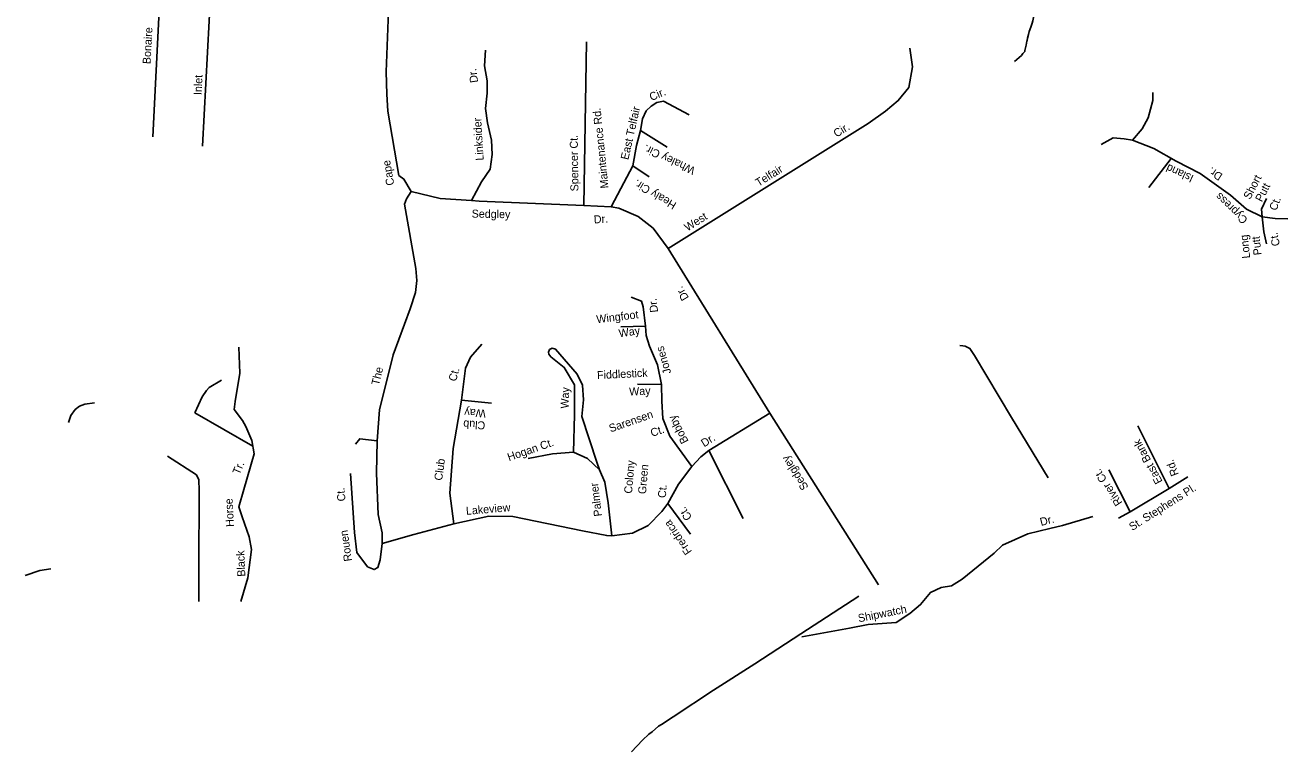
# Model space of a CAD drawing. Extents: x 2308163 to 2335412, y -96774 to 127732.
# Drawn here: x 2321289 to 2322583, y 13023 to 13768 of the extents above; entities that cross this region are included whole.
import ezdxf

# ---------------------------------------------------------------- set-up
doc = ezdxf.new("R2010")
doc.units = 0
doc.layers.add('Old_Level_10', color=7, linetype='Continuous')
doc.layers.add('Old_Level_35', color=7, linetype='Continuous')

msp = doc.modelspace()

# ---------------------------------------------------------------- linework, layer by layer
at = {"layer": 'Old_Level_35'}
for points in [[(2321470.9, 13644.1), (2321479.2, 13805.1), (2321483.9, 13860.9), (2321484.1, 13918.6), (2321488.9, 13978), (2321484.4, 14035), (2321484.8, 14072.5), (2321494.1, 14104.3), (2321497.9, 14132.5), (2321498.4, 14173.8)], [(2321419.9, 13653.8), (2321443.4, 14123.4), (2321438.5, 14164.8)], [(2321684.8, 13597.6), (2321677.3, 13610.4), (2321672.2, 13614.2), (2321660.9, 13680.1), (2321659.9, 13697.4), (2321659.1, 13720.5), (2321661, 13773.8), (2321660.4, 13787.4), (2321658.4, 13821), (2321656.2, 13849.4), (2321657.3, 13864.5), (2321663, 13879.5), (2321675.1, 13895.3), (2321684, 13910.7), (2321692.1, 13931.9), (2321701.8, 13970.3), (2321711.6, 14009.8), (2321724.8, 14060.6), (2321735.9, 14109.5), (2321739.7, 14137)], [(2322316.1, 13752.6), (2322316.7, 13754.8), (2322317.6, 13758.5), (2322318.4, 13761.7), (2322320, 13766.2), (2322321.4, 13770.4), (2322322.2, 13772.7), (2322322.5, 13774.4), (2322322.7, 13775.9), (2322322.5, 13778.1), (2322322.8, 13780.6), (2322321.8, 13790.4), (2322320.2, 13807), (2322318.2, 13825.5), (2322317.3, 13831.8), (2322317.3, 13840), (2322317, 13849.8), (2322317.7, 13866), (2322318.5, 13891.5), (2322320.1, 13927.7), (2322321.1, 13953.3)], [(2321861.7, 13583.4), (2321864.4, 13751.2)], [(2322303.2, 13731.1), (2322310.3, 13737.1), (2322311.8, 13739.1), (2322313.1, 13740.6), (2322313.9, 13741.3), (2322313.9, 13742.3), (2322315.1, 13747.8), (2322315.9, 13751.8), (2322316.1, 13752.6)], [(2321760.9, 13742.6), (2321759.8, 13726.4), (2321762.5, 13711.1), (2321762.5, 13698.6), (2321761, 13682.9), (2321763.1, 13668.2), (2321767.2, 13650.2), (2321767.7, 13635.6), (2321765.6, 13620.4), (2321756.8, 13607.7), (2321746.7, 13588.4)], [(2321948.2, 13539.1), (2322153.3, 13667.4), (2322171, 13679.9), (2322184, 13690.9), (2322194.9, 13704.2), (2322198.8, 13725.5), (2322195.8, 13744.5)], [(2322424.1, 13650.4), (2322434.1, 13661.8), (2322440.3, 13673.2), (2322445.2, 13691.1), (2322444.9, 13699)], [(2321889.9, 13581.9), (2321899.5, 13600.7), (2321911.8, 13623.9), (2321915.7, 13644.7), (2321919.9, 13660.3), (2321921.9, 13672.2), (2321925.8, 13680.5), (2321930.7, 13685), (2321936.6, 13689), (2321943.5, 13690.3), (2321969.7, 13676.3)], [(2321919.9, 13660.3), (2321947.1, 13643.1)], [(2322392.1, 13645.7), (2322404.5, 13652.7), (2322415.7, 13651.8), (2322424.1, 13650.4), (2322446.1, 13641.7), (2322469, 13628.7), (2322493.5, 13616.2), (2322524.6, 13593.9), (2322541.1, 13579.6), (2322557.3, 13571.6), (2322556.5, 13579.6), (2322561.6, 13590.5)], [(2322441, 13601.6), (2322464, 13631.5)], [(2321911.8, 13623.9), (2321928.7, 13612.8)], [(2321684.8, 13597.6), (2321679.8, 13590), (2321678, 13584.8), (2321689.4, 13518.5), (2321690.5, 13506.4), (2321689, 13493.9), (2321683.8, 13477.3), (2321666.4, 13430.2), (2321652.4, 13373.7), (2321649.7, 13341.9), (2321649.1, 13308.9), (2321650.8, 13266.5), (2321654.9, 13247.5), (2321655, 13236.5), (2321652.9, 13219.8), (2321650.5, 13212), (2321646.8, 13210), (2321640.1, 13212.9), (2321629, 13227.4), (2321626.6, 13247.9), (2321622.4, 13308.3)], [(2321972.4, 13315.5), (2321981.7, 13325.6), (2321989.8, 13332.2), (2322052.4, 13370.3), (2321948.2, 13539.1), (2321932.7, 13560), (2321917.4, 13572.1), (2321897.7, 13580.6), (2321889.9, 13581.9), (2321861.7, 13583.4), (2321754.5, 13587.6), (2321746.7, 13588.4), (2321714.3, 13590.6), (2321684.8, 13597.6)], [(2322557.3, 13571.6), (2322558.9, 13556.1), (2322561.6, 13543.8)], [(2322557.3, 13571.6), (2322570.5, 13570.1), (2322583.4, 13569.5)], [(2321655, 13236.5), (2321687.3, 13245.8), (2321728.6, 13257), (2321764.4, 13264.6), (2321789.1, 13264.3), (2321860.3, 13249.7), (2321885.3, 13244.7), (2321890.6, 13244.5), (2321911.6, 13247.4), (2321927.6, 13255.2), (2321941.7, 13269.4), (2321947.8, 13277.6), (2321958.7, 13297.6), (2321972.4, 13315.5), (2321949.9, 13346.6), (2321942.7, 13364.7), (2321941.7, 13382.5), (2321941.3, 13399.8), (2321937.3, 13419.8), (2321929, 13439), (2321925.7, 13450.1), (2321925, 13459.5), (2321922.6, 13479.5), (2321920.7, 13485.3), (2321910.3, 13489.4)], [(2321925, 13459.5), (2321899.8, 13458.8)], [(2321510.1, 13177.1), (2321517.4, 13201.4), (2321521.1, 13230.5), (2321518.8, 13243.5), (2321511.3, 13263.9), (2321508, 13274.1), (2321513.2, 13292.2), (2321523.6, 13328.5), (2321521.3, 13342.3), (2321515.2, 13356.8), (2321511.9, 13362.8), (2321503.2, 13374.1), (2321504.4, 13382.3), (2321509, 13411.5), (2321508.1, 13438.1)], [(2321728.6, 13257), (2321724.5, 13288.2), (2321727.7, 13334.2), (2321736.2, 13383.6), (2321740.4, 13416.5), (2321745.6, 13427.8), (2321757, 13441)], [(2321851.2, 13330.4), (2321852, 13368.6), (2321852, 13399.5), (2321841.6, 13417.2), (2321827.8, 13428.1), (2321825.8, 13430.8), (2321825.4, 13432.9), (2321826.5, 13435.5), (2321829.2, 13437), (2321832.8, 13435.8), (2321855, 13410.4), (2321860.4, 13399.2), (2321861.4, 13384), (2321859.8, 13366.8), (2321874.9, 13320.2), (2321877.8, 13312.2)], [(2322337.6, 13304), (2322300.3, 13366), (2322262.1, 13429.4), (2322257.5, 13436.8), (2322255.5, 13437.8), (2322252.8, 13438.9), (2322250.3, 13439.2), (2322247.1, 13439.8)], [(2321462.9, 13370.8), (2321470.5, 13386.9), (2321474.9, 13393.5), (2321477.6, 13396.7), (2321490.2, 13404.2)], [(2321941.3, 13399.8), (2321916.7, 13400.1)], [(2321736.2, 13383.6), (2321767, 13380.5)], [(2321333.5, 13360.6), (2321335.9, 13367.9), (2321340.3, 13374.1), (2321344.8, 13377.4), (2321350.2, 13379.7), (2321360, 13380.9)], [(2321462.9, 13370.8), (2321522.3, 13336.5)], [(2322052.4, 13370.3), (2322163.7, 13194.3)], [(2322429.6, 13357.3), (2322461.9, 13293.1), (2322480.9, 13305.2)], [(2321649.7, 13341.9), (2321632, 13344.1), (2321627.6, 13338.5)], [(2321989.8, 13332.2), (2322025.1, 13262.3)], [(2321434.8, 13326.3), (2321464.6, 13307.2), (2321467, 13302), (2321467.4, 13290.9), (2321467.2, 13211), (2321467.1, 13177.2)], [(2321890.6, 13244.5), (2321886.6, 13278.4), (2321883.1, 13299.5), (2321877.8, 13312.2), (2321865.6, 13323.7), (2321851.2, 13330.4), (2321829.6, 13328.6), (2321804.8, 13323.7)], [(2322421.8, 13269), (2322399.9, 13312.2)], [(2322461.9, 13293.1), (2322421.8, 13269), (2322409.9, 13262.5)], [(2321947.8, 13277.6), (2321971.1, 13246.4)], [(2322085.3, 13141.1), (2322134, 13150), (2322153.2, 13153.6), (2322182, 13155.8), (2322196.1, 13164.9), (2322207, 13174), (2322217, 13186.4), (2322228, 13191.4), (2322238.7, 13193.1), (2322249.5, 13200.2), (2322282.3, 13226.6), (2322291.1, 13234.8), (2322317, 13246.6), (2322339.5, 13252.2), (2322352.3, 13255), (2322383.4, 13264.5)], [(2321289.1, 13203.9), (2321303.9, 13209.1), (2321315.3, 13210.6)], [(2322143.5, 13182.6), (2322084.3, 13144), (2322037, 13113.4), (2321994.8, 13086.1), (2321953.4, 13058.9), (2321941.2, 13050.9), (2321938.4, 13049.2), (2321931.8, 13043.6), (2321928.4, 13041.2), (2321921.8, 13034.9), (2321910.6, 13023.1)]]:
    msp.add_lwpolyline(points, dxfattribs=at)

# ---------------------------------------------------------------- texts
at = {"layer": 'Old_Level_10'}
for s, height, rotation, p in [('Bonaire', 8.2, 86.8529, (2321417.5, 13728.1)), ('Dr.', 8.2, 98.3115, (2321753.4, 13709.7)), ('Inlet', 8.2, 87.8162, (2321470, 13696.4)), ('Cir.', 8.2, 22.8854, (2321931, 13690.3)), ('Maintenance Rd.', 8.202, 95.7048, (2321887.1, 13601.2)), ('East Telfair ', 8.202, 77.2768, (2321907.3, 13629.6)), ('Linksider', 8.2, 93.4684, (2321759.1, 13629.6)), ('Cir.', 8.2, 31.7692, (2322120.8, 13652.8)), ('Spencer Ct.', 8.202, 90.7324, (2321856.2, 13597.8)), ('Whaley Cir.', 8.202, 154.835, (2321976.7, 13621.9)), ('Cape', 8.2, 99.9628, (2321667.5, 13604.5)), ('Telfair', 8.2, 31.8069, (2322040.8, 13602.4)), (' Island ', 8.2, 155.2034, (2322490.4, 13612.6)), ('Dr.', 8.2, 146.8638, (2322517.3, 13615.1)), ('Healy Cir.', 8.2, 149.1209, (2321957.4, 13585.7)), ('Short', 8.2, 62.5056, (2322544.7, 13588.8)), ('Putt', 8.2, 62.5056, (2322556.8, 13586.3)), ('Cypress', 8.2, 136.1992, (2322543, 13569.3)), ('Sedgley', 8.2, 358.9794, (2321746.7, 13570.9)), ('Ct.', 8.2, 68.6681, (2322571.6, 13577.3)), ('Dr.', 8.2, 3.7721, (2321872.2, 13564.8)), ('West', 8.2, 32.3643, (2321968, 13556.5)), ('Long', 8.2, 95.9768, (2322544.9, 13529.4)), ('Putt', 8.2, 95.9768, (2322556.6, 13532.7)), ('Ct.', 8.2, 101.7692, (2322575.5, 13542.5)), ('Dr.', 8.2, 121.0201, (2321969.7, 13488.7)), ('Dr.', 8.2, 96.5311, (2321937.9, 13474)), ('Wingfoot ', 8.2, 6.8876, (2321875.1, 13462.5)), ('Way', 8.2, 8.3091, (2321898.1, 13448.1)), ('Jones', 8.2, 106.3222, (2321951.4, 13411.7)), ('The ', 8.2, 76.327, (2321651.7, 13398.3)), ('Ct.', 8.2, 75.0685, (2321730.7, 13402.3)), ('Fiddlestick', 8.202, 2.8383, (2321875.5, 13405.2)), ('Way', 8.2, 87.7119, (2321846, 13374.9)), ('Way', 8.2, 2.8383, (2321908.4, 13388.3)), ('Way', 8.2, 176.6967, (2321761.4, 13373.9)), ('Sarensen', 8.2, 19.2289, (2321889.2, 13350.5)), ('Club', 8.2, 176.6967, (2321760.9, 13361.7)), ('Bobby', 8.2, 117.1145, (2321969.3, 13341.5)), ('Ct.', 8.2, 19.2289, (2321931.7, 13345.9)), ('Dr.', 8.2, 32.3018, (2321985.1, 13335.2)), ('East Bank', 8.2, 118.3259, (2322455.3, 13300.3)), ('Hogan Ct.', 8.2, 19.0033, (2321785, 13321)), ('Tr.', 8.2, 66.8835, (2321508.7, 13306.6)), ('Club ', 8.2, 82.3139, (2321716.4, 13300.8)), ('Colony', 8.2, 85.3278, (2321911.1, 13287.6)), ('Sedgley', 8.2, 122.9112, (2322092.4, 13294.6)), ('Rd.', 8.2, 110.7645, (2322471.8, 13307.6)), ('Green ', 8.2, 85.3278, (2321925.4, 13287.1)), ('River Ct.', 8.2, 123.4059, (2322414.2, 13278.5)), ('Ct.', 8.2, 94.6733, (2321617.4, 13280.2)), ('Palmer', 8.2, 97.0173, (2321880.4, 13264.9)), ('Ct.', 8.2, 85.3278, (2321945.7, 13283.1)), ('St. Stephens Pl.', 8.202, 32.4762, (2322423.9, 13249.4)), ('Horse', 8.2, 92.966, (2321503.1, 13253.9)), ('Lakeview', 8.2, 4.7502, (2321741.2, 13266)), ('Ct.', 8.2, 124.4823, (2321973.1, 13263.6)), ('Fredrica', 8.2, 124.4823, (2321972.9, 13228.5)), ('Dr.', 8.2, 14.4843, (2322330.5, 13254.6)), ('Rouen', 8.2, 98.3217, (2321624.1, 13218.9)), ('Black', 8.2, 92.67, (2321514.8, 13202.8)), ('Shipwatch', 8.2, 11.3903, (2322143.7, 13155.8))]:
    msp.add_text(s, height=height, rotation=rotation, dxfattribs=at).set_placement(p)

doc.saveas('drawing.dxf')
